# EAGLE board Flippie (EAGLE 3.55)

Size 45.7 x 42.85 mm. Coordinates in mm from the lower left corner, seen from the top.
Outline: 0,0 45.7,0 45.7,42.85 0,42.85 0,0
Copper layers used: 

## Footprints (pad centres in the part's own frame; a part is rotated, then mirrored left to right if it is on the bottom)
GEL = drill 1.295 pad 3.048 round:  0,0
RM2,5 = drill 0.813 pad 1.422 round:  0,0;  2.54,0
L8 = drill 0.813 pad 1.6 round:  -3.81,-3.81 | drill 0.813 pad 1.6 octagon:  -1.27,-3.81;  1.27,-3.81;  3.81,-3.81;  3.81,3.81;  1.27,3.81;  -1.27,3.81;  -3.81,3.81
D_3MM = drill 0.813 pad 1.422 round:  0,0;  2.54,0
H-1POL = drill 0.813 pad 1.422 round:  0,0;  5.08,0

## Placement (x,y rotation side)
+  +  [GEL]  12.7,19.05 0 top
C1  C100NK  [RM2,5]  30.48,19.05 0 top
IC1  12C509P  [L8]  34.29,8.89 0 top
LED1  rot  [D_3MM]  36.83,26.67 0 top
LED2  rot  [D_3MM]  20.32,7.62 0 top
LED3  rot  [D_3MM]  25.4,26.67 0 top
LED4  rot  [D_3MM]  36.83,36.83 0 top
LED5  rot  [D_3MM]  25.4,36.83 0 top
N2  -  [GEL]  12.7,25.4 0 top
S1  Mode  [H-1POL]  6.35,8.89 0 top

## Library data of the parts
+ C1 LED1-LED5 N2 = holgnorm
IC1 = PIC
S1 = taster

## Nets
+UB: +. C1. IC1. LED1. LED2. LED3. LED4. LED5.
GND: C1. IC1. N2. S1.
N$5: IC1. LED5.
N$6: IC1. LED4.
N$7: IC1. LED3.
N$8: IC1. LED2.
N$9: IC1. LED1.
N$11: IC1. S1.

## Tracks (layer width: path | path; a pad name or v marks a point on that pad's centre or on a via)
+UB  (7 unrouted)
GND  (3 unrouted)
N$5  (1 unrouted)
N$6  (1 unrouted)
N$7  (1 unrouted)
N$8  (1 unrouted)
N$9  (1 unrouted)
N$11  (1 unrouted)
